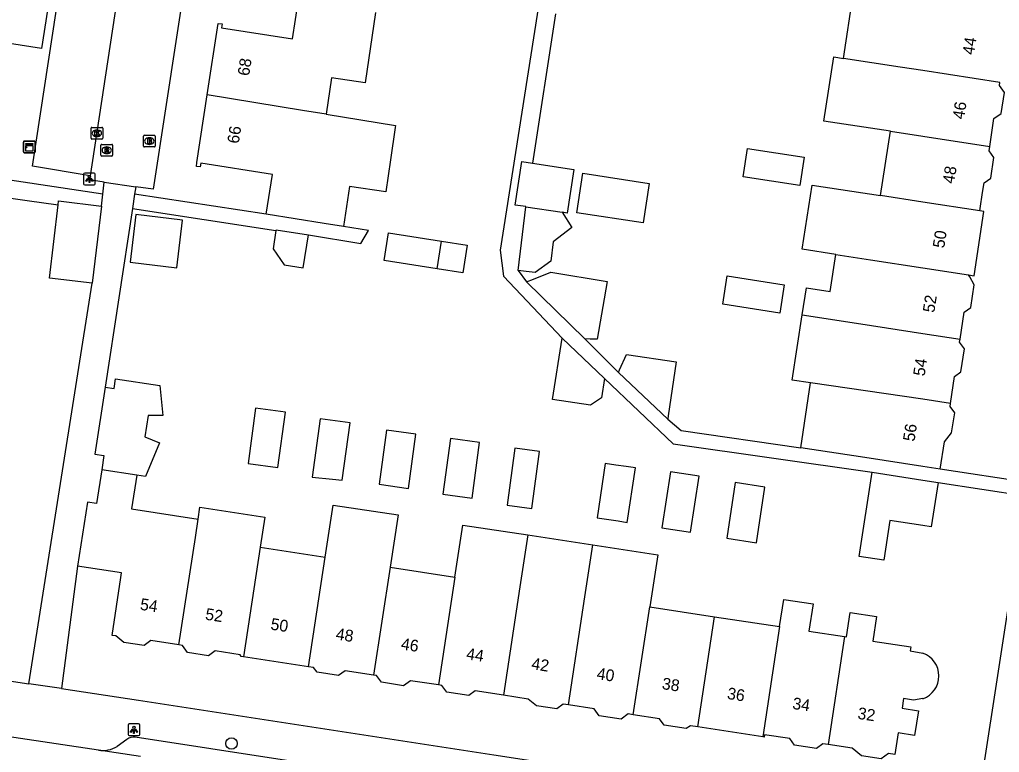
# Model space of a CAD drawing. Extents: x 161486 to 162249, y 379484 to 380829.
# Drawn here: x 161923 to 162006.5, y 380546.9 to 380609.4 of the extents above; entities that cross this region are included whole.
import ezdxf

# ---------------------------------------------------------------- set-up
doc = ezdxf.new("R2010")
doc.units = 0
for name, color, linetype in [('IMGEO_Boom', 7, 'Continuous'), ('IMGEO_Brandkraan', 7, 'Continuous'), ('IMGEO_Kast', 7, 'Continuous'), ('IMGEO_Kolk', 7, 'Continuous'), ('IMGEO_Lichtpunt', 7, 'Continuous'), ('IMGEO_Pand', 7, 'Continuous'), ('IMGEO_Pand_nummerreeks', 7, 'Continuous'), ('IMGEO_Parkeervlak_open', 7, 'Continuous'), ('IMGEO_Rijbaan_lokaal_open', 7, 'Continuous'), ('IMGEO_Rioolput', 7, 'Continuous'), ('IMGEO_Voetpad_open', 7, 'Continuous')]:
    doc.layers.add(name, color=color, linetype=linetype)

msp = doc.modelspace()

# ---------------------------------------------------------------- linework, layer by layer
at = {"layer": 'IMGEO_Boom'}
msp.add_circle((161941.042, 380547.667), 0.489, dxfattribs=at)
at = {"layer": 'IMGEO_Brandkraan'}
for p, q in [((161933.53, 380598.607), (161933.53, 380599.459)), ((161933.605, 380599.533), (161934.457, 380599.533)), ((161934.018, 380599.313), (161934.043, 380599.313)), ((161934.531, 380599.459), (161934.531, 380598.607)), ((161934.457, 380598.533), (161933.605, 380598.533)), ((161934.041, 380598.753), (161934.016, 380598.753))]:
    msp.add_line(p, q, dxfattribs=at)
for points in [[(161933.53, 380598.607), (161933.53, 380599.459)], [(161933.605, 380599.533), (161934.457, 380599.533)], [(161933.878, 380599.233), (161933.878, 380598.833), (161934.091, 380598.833)], [(161934.109, 380599.233), (161933.878, 380599.233)], [(161934.057, 380599.152), (161934.003, 380599.152), (161934.003, 380599.076)], [(161934.003, 380599.076), (161934.056, 380599.076)], [(161934.065, 380599), (161934.003, 380599), (161934.003, 380598.919)], [(161934.003, 380598.919), (161934.065, 380598.919)], [(161934.531, 380599.459), (161934.531, 380598.607)], [(161934.457, 380598.533), (161933.605, 380598.533)]]:
    msp.add_lwpolyline(points, dxfattribs=at)
for centre, radius, start, end in [((161933.607, 380599.457), 0.0765, 91.55205, 178.44795), ((161933.607, 380599.457), 0.0765, 91.55205, 178.44795), ((161934.058, 380599.114), 0.0379, 267.82845, 90.93552), ((161934.066, 380598.959), 0.0404, 269.87594, 90.50774), ((161934.097, 380599.084), 0.251, 268.66757, 293.53466), ((161934.113, 380599.088), 0.145, 59.4692, 91.53667), ((161934.138, 380599.135), 0.0922, 285.51372, 58.15012), ((161934.143, 380598.943), 0.105, 301.31148, 78.98903), ((161934.455, 380599.457), 0.0765, 1.55205, 88.44795), ((161934.455, 380599.457), 0.0765, 1.55205, 88.44795), ((161933.607, 380598.609), 0.0765, 181.55205, 268.44795), ((161933.607, 380598.609), 0.0765, 181.55205, 268.44795), ((161934.455, 380598.609), 0.0765, 271.55205, 358.44795), ((161934.455, 380598.609), 0.0765, 271.55205, 358.44795)]:
    msp.add_arc(centre, radius, start, end, dxfattribs=at)
for centre, major_axis, ratio, start_param, end_param in [((161934.017, 380599.033), (-0.387, 0.002), 0.722429, 4.712389, 7.853982), ((161934.042, 380599.033), (-0.39, 0.002), 0.717154, 1.570796, 4.712389)]:
    msp.add_ellipse(centre, major_axis=major_axis, ratio=ratio, start_param=start_param, end_param=end_param, dxfattribs=at)
at = {"layer": 'IMGEO_Kast'}
for p, q in [((161923.289, 380598.109), (161923.289, 380598.95)), ((161923.289, 380598.95), (161923.289, 380598.109)), ((161923.364, 380599.034), (161924.205, 380599.034)), ((161924.205, 380599.034), (161923.364, 380599.034)), ((161924.289, 380598.959), (161924.289, 380598.118)), ((161924.289, 380598.118), (161924.289, 380598.959)), ((161924.214, 380598.034), (161923.373, 380598.034)), ((161923.373, 380598.034), (161924.214, 380598.034))]:
    msp.add_line(p, q, dxfattribs=at)
for points in [[(161923.484, 380598.824), (161924.084, 380598.824), (161924.084, 380598.739), (161923.484, 380598.739), (161923.484, 380598.824)], [(161923.484, 380598.649), (161924.084, 380598.649), (161924.084, 380598.16), (161923.484, 380598.16), (161923.484, 380598.649)]]:
    msp.add_lwpolyline(points, dxfattribs=at)
msp.add_circle((161923.568, 380598.498), 0.0377, dxfattribs=at)
for centre, start, end in [((161923.367, 380598.956), 92.4484, 184.28452), ((161923.367, 380598.956), 92.4484, 184.28452), ((161924.211, 380598.956), 2.4484, 94.28452), ((161924.211, 380598.956), 2.4484, 94.28452), ((161923.367, 380598.112), 182.4484, 274.28452), ((161923.367, 380598.112), 182.4484, 274.28452), ((161924.211, 380598.112), 272.4484, 4.28452), ((161924.211, 380598.112), 272.4484, 4.28452)]:
    msp.add_arc(centre, 0.0779, start, end, dxfattribs=at)
at = {"layer": 'IMGEO_Kolk'}
for p, q in [((161929.058, 380599.272), (161929.058, 380600.124)), ((161929.133, 380600.198), (161929.985, 380600.198)), ((161929.546, 380599.978), (161929.571, 380599.978)), ((161930.059, 380600.124), (161930.059, 380599.272)), ((161929.985, 380599.198), (161929.133, 380599.198)), ((161929.569, 380599.418), (161929.544, 380599.418))]:
    msp.add_line(p, q, dxfattribs=at)
for points in [[(161929.058, 380599.272), (161929.058, 380600.124)], [(161929.133, 380600.198), (161929.985, 380600.198)], [(161929.379, 380599.898), (161929.502, 380599.898), (161929.502, 380599.747), (161929.632, 380599.898), (161929.796, 380599.898), (161929.65, 380599.747), (161929.803, 380599.498), (161929.651, 380599.498), (161929.566, 380599.662), (161929.502, 380599.595), (161929.502, 380599.498), (161929.379, 380599.498), (161929.379, 380599.898)], [(161930.059, 380600.124), (161930.059, 380599.272)], [(161929.985, 380599.198), (161929.133, 380599.198)]]:
    msp.add_lwpolyline(points, dxfattribs=at)
for centre, start, end in [((161929.135, 380600.122), 91.55205, 178.44795), ((161929.135, 380600.122), 91.55205, 178.44795), ((161929.983, 380600.122), 1.55205, 88.44795), ((161929.983, 380600.122), 1.55205, 88.44795), ((161929.135, 380599.274), 181.55205, 268.44795), ((161929.135, 380599.274), 181.55205, 268.44795), ((161929.983, 380599.274), 271.55205, 358.44795), ((161929.983, 380599.274), 271.55205, 358.44795)]:
    msp.add_arc(centre, 0.0765, start, end, dxfattribs=at)
for centre, major_axis, ratio, start_param, end_param in [((161929.545, 380599.698), (-0.387, 0.002), 0.722429, 4.712389, 7.853982), ((161929.57, 380599.698), (-0.39, 0.002), 0.717154, 1.570796, 4.712389)]:
    msp.add_ellipse(centre, major_axis=major_axis, ratio=ratio, start_param=start_param, end_param=end_param, dxfattribs=at)
at = {"layer": 'IMGEO_Lichtpunt'}
for p, q in [((161928.425, 380596.205), (161928.425, 380595.398)), ((161928.425, 380596.205), (161928.425, 380595.398)), ((161929.327, 380596.3), (161928.519, 380596.3)), ((161929.327, 380596.3), (161928.519, 380596.3)), ((161929.421, 380595.398), (161929.421, 380596.205)), ((161929.421, 380595.398), (161929.421, 380596.205)), ((161928.519, 380595.304), (161929.327, 380595.304)), ((161928.519, 380595.304), (161929.327, 380595.304)), ((161932.214, 380549.237), (161932.214, 380548.43)), ((161932.214, 380549.237), (161932.214, 380548.43)), ((161933.116, 380549.332), (161932.308, 380549.332)), ((161933.116, 380549.332), (161932.308, 380549.332)), ((161933.21, 380548.43), (161933.21, 380549.237)), ((161933.21, 380548.43), (161933.21, 380549.237)), ((161932.308, 380548.336), (161933.116, 380548.336)), ((161932.308, 380548.336), (161933.116, 380548.336))]:
    msp.add_line(p, q, dxfattribs=at)
for points in [[(161928.799, 380595.869), (161928.838, 380595.841), (161928.65, 380595.579), (161928.612, 380595.606), (161928.799, 380595.869)], [(161928.901, 380595.821), (161928.948, 380595.821), (161928.948, 380595.499), (161928.901, 380595.499), (161928.901, 380595.821)], [(161929.011, 380595.841), (161929.049, 380595.868), (161929.236, 380595.606), (161929.197, 380595.578), (161929.011, 380595.841)], [(161932.588, 380548.901), (161932.627, 380548.873), (161932.439, 380548.611), (161932.401, 380548.638), (161932.588, 380548.901)], [(161932.69, 380548.853), (161932.737, 380548.853), (161932.737, 380548.531), (161932.69, 380548.531), (161932.69, 380548.853)], [(161932.8, 380548.873), (161932.838, 380548.9), (161933.025, 380548.638), (161932.986, 380548.61), (161932.8, 380548.873)]]:
    msp.add_lwpolyline(points, dxfattribs=at)
for centre in [(161928.924, 380596.003), (161932.713, 380549.035)]:
    msp.add_circle(centre, 0.0994, dxfattribs=at)
for centre, start, end in [((161928.519, 380596.205), 90, 180), ((161928.519, 380596.205), 90, 180), ((161929.327, 380596.205), 0, 90), ((161929.327, 380596.205), 0, 90), ((161928.519, 380595.398), 180, 270), ((161928.519, 380595.398), 180, 270), ((161929.327, 380595.398), 270, 0), ((161929.327, 380595.398), 270, 360), ((161932.308, 380549.237), 90, 180), ((161932.308, 380549.237), 90, 180), ((161933.116, 380549.237), 0, 90), ((161933.116, 380549.237), 0, 90), ((161932.308, 380548.43), 180, 270), ((161932.308, 380548.43), 180, 270), ((161933.116, 380548.43), 270, 0), ((161933.116, 380548.43), 270, 360)]:
    msp.add_arc(centre, 0.0946, start, end, dxfattribs=at)
at = {"layer": 'IMGEO_Pand'}
for points in [[(161917.716, 380621.282), (161923.826, 380620.34), (161923.776, 380620.014), (161923.448, 380620.062), (161922.489, 380614.014), (161925.86, 380613.48), (161924.84, 380606.93), (161919.899, 380607.691), (161918.824, 380607.857), (161915.718, 380608.336)], [(161993.216, 380606.087), (161994.058, 380611.562), (161994.86, 380611.439)], [(161938.975, 380602.968), (161939.91, 380609.067), (161940.237, 380609.017), (161940.187, 380608.69), (161946.233, 380607.761), (161946.743, 380611.081)], [(161953.318, 380610.009), (161952.424, 380604.011), (161949.568, 380604.437), (161949.104, 380601.327)], [(161997.221, 380599.865), (161991.558, 380600.737), (161992.398, 380606.213), (161993.216, 380606.087)], [(162006.562, 380604.033), (162000, 380605.043), (161998.061, 380605.341), (161993.216, 380606.087)], [(162005.693, 380598.561), (162006.059, 380600.946), (162006.667, 380601.392), (162006.942, 380603.185), (162006.52, 380603.76), (162006.562, 380604.033)], [(161944, 380592.793), (161944.536, 380596.18), (161938.417, 380597.148), (161938.367, 380596.825), (161938.042, 380596.875), (161938.09, 380597.2), (161938.975, 380602.968)], [(161949.104, 380601.327), (161947.102, 380601.651), (161938.975, 380602.968)], [(161949.104, 380601.327), (161955.033, 380600.366), (161955.006, 380600.189), (161954.598, 380597.445), (161954.189, 380594.702), (161951.104, 380595.161), (161950.596, 380591.749)], [(161996.38, 380594.389), (161997.221, 380599.865)], [(161997.221, 380599.865), (162000, 380599.437), (162005.693, 380598.561)], [(161989.866, 380597.662), (161989.495, 380595.251), (161984.679, 380595.993), (161985.051, 380598.404), (161989.866, 380597.662)], [(162004.844, 380593.087), (162004.872, 380593.269), (162005.083, 380594.644), (162005.208, 380595.459), (162005.782, 380595.88), (162006.053, 380597.646), (162005.639, 380598.209), (162005.693, 380598.561)], [(161966.136, 380593.438), (161966.123, 380593.44), (161965.22, 380593.579), (161965.792, 380597.302), (161966.698, 380597.162)], [(161966.698, 380597.162), (161970.22, 380596.62), (161969.648, 380592.898), (161969.24, 380592.961)], [(161976.665, 380595.411), (161976.147, 380592.048), (161970.492, 380592.918), (161971.01, 380596.282), (161976.665, 380595.411)], [(161992.584, 380589.368), (161989.706, 380589.811), (161990.549, 380595.286), (161996.38, 380594.389)], [(161926.255, 380593.587), (161926.296, 380593.93), (161929.955, 380593.489)], [(162004.844, 380593.087), (162000, 380593.832), (161996.38, 380594.389)], [(161929.162, 380586.915), (161925.503, 380587.356), (161926.255, 380593.587)], [(161929.955, 380593.489), (161929.162, 380586.915)], [(161965.481, 380587.998), (161966.136, 380593.438)], [(161966.136, 380593.438), (161969.24, 380592.961)], [(162003.897, 380587.627), (162004.366, 380587.555), (162005.205, 380593.031), (162004.844, 380593.087)], [(161936.86, 380592.297), (161932.883, 380592.777), (161932.391, 380588.699), (161936.368, 380588.219), (161936.86, 380592.297)], [(161950.596, 380591.749), (161948.939, 380592.011), (161944, 380592.793)], [(161969.24, 380592.961), (161970.049, 380591.657), (161968.465, 380590.427), (161968.267, 380588.784), (161966.94, 380587.822), (161966.174, 380587.914), (161965.481, 380587.998)], [(161944.827, 380591.415), (161944.576, 380589.839), (161945.537, 380588.487), (161947.156, 380588.231), (161947.598, 380591.024)], [(161944.827, 380591.415), (161944.834, 380591.462), (161947.598, 380591.024)], [(161958.576, 380588.135), (161954.047, 380588.85), (161954.421, 380591.222), (161958.951, 380590.506)], [(161958.951, 380590.506), (161961.139, 380590.16), (161960.764, 380587.789), (161958.576, 380588.135)], [(161958.576, 380588.135), (161958.951, 380590.506)], [(161989.706, 380584.207), (161990.06, 380586.509), (161992.096, 380586.196), (161992.584, 380589.368)], [(161992.584, 380589.368), (161995.54, 380588.913), (162000, 380588.227), (162003.897, 380587.627)], [(161966.184, 380587.031), (161966.795, 380587.263), (161968.263, 380587.854), (161973.073, 380587.046), (161972.214, 380582.128), (161971.61, 380582.144), (161971.181, 380582.156)], [(161988.155, 380586.787), (161987.783, 380584.372), (161982.94, 380585.117), (161983.311, 380587.532), (161988.155, 380586.787)], [(162003.162, 380582.135), (162003.515, 380584.435), (162004.082, 380584.851), (162004.379, 380586.788), (162004, 380587.448), (162003.897, 380587.627)], [(161971.181, 380582.156), (161966.184, 380587.031)], [(161990.423, 380578.414), (161988.851, 380578.656), (161989.706, 380584.207)], [(161989.706, 380584.207), (161994.7, 380583.438), (162000, 380582.622), (162003.162, 380582.135)], [(161972.841, 380578.787), (161972.586, 380577.129), (161971.639, 380576.511), (161968.421, 380577.007), (161969.225, 380582.226)], [(161969.225, 380582.226), (161972.841, 380578.787)], [(162002.35, 380576.655), (162002.705, 380578.968), (162003.234, 380579.356), (162003.536, 380581.324), (162003.124, 380581.885), (162003.162, 380582.135)], [(161974.025, 380579.289), (161974.128, 380579.517), (161974.726, 380580.847), (161978.947, 380580.21), (161978.277, 380575.591), (161978.237, 380575.315)], [(161978.237, 380575.315), (161974.025, 380579.289)], [(161930.261, 380578.044), (161929.388, 380572.33), (161930.159, 380572.212), (161929.975, 380571.007)], [(161930.261, 380578.044), (161931.022, 380577.928), (161931.151, 380578.768), (161934.927, 380578.191), (161935.183, 380575.623), (161933.933, 380575.623), (161933.658, 380573.824), (161934.909, 380573.289), (161933.689, 380570.439), (161932.957, 380570.551)], [(161989.575, 380572.885), (161990.423, 380578.414)], [(162002.35, 380576.655), (162000, 380577.017), (161990.423, 380578.414)], [(162001.469, 380571.06), (162001.825, 380573.376), (162002.444, 380574.149), (162002.708, 380575.867), (162002.312, 380576.406), (162002.35, 380576.655)], [(161942.444, 380571.541), (161944.986, 380571.195), (161945.628, 380575.915), (161943.086, 380576.26), (161942.444, 380571.541)], [(161947.927, 380570.373), (161949.647, 380570.205), (161950.488, 380570.123), (161951.151, 380574.995), (161948.603, 380575.342), (161947.927, 380570.373)], [(161956.132, 380569.422), (161956.759, 380574.034), (161954.244, 380574.377), (161953.616, 380569.765), (161956.132, 380569.422)], [(161961.552, 380568.582), (161962.196, 380573.322), (161959.699, 380573.662), (161959.054, 380568.922), (161961.552, 380568.582)], [(161967.316, 380572.573), (161965.198, 380572.861), (161964.534, 380567.979), (161966.652, 380567.691), (161967.316, 380572.573)], [(162001.469, 380571.06), (162000, 380571.285), (161995.058, 380572.043), (161989.575, 380572.885)], [(161973.801, 380571.411), (161972.904, 380571.542), (161972.222, 380566.912), (161974.016, 380566.638), (161974.776, 380566.522), (161975.485, 380571.164), (161974.698, 380571.279), (161973.801, 380571.411)], [(161929.975, 380571.007), (161929.534, 380568.12), (161928.743, 380568.241), (161927.911, 380562.794)], [(161932.957, 380570.551), (161929.975, 380571.007)], [(161932.957, 380570.551), (161932.516, 380567.664), (161938.191, 380566.797)], [(161980.183, 380565.688), (161980.909, 380570.448), (161978.468, 380570.821), (161977.741, 380566.061), (161980.183, 380565.688)], [(162001.293, 380569.928), (162000.713, 380566.149), (162000, 380566.259), (161997.184, 380566.691), (161996.663, 380563.299), (161994.567, 380563.62), (161995.667, 380570.791)], [(161995.667, 380570.791), (162000, 380570.126), (162001.293, 380569.928)], [(161986.523, 380569.533), (161983.986, 380569.92), (161983.284, 380565.16), (161985.797, 380564.776), (161986.523, 380569.533)], [(161949.025, 380563.55), (161949.704, 380567.998), (161955.24, 380567.152), (161954.56, 380562.704)], [(161938.191, 380566.797), (161938.346, 380567.818), (161943.881, 380566.973), (161943.488, 380564.396)], [(161936.553, 380556.067), (161937.953, 380565.242), (161938.191, 380566.797)], [(161960.096, 380561.858), (161960.773, 380566.29), (161966.308, 380565.444)], [(161966.308, 380565.444), (161965.632, 380561.012), (161964.223, 380551.78)], [(161966.308, 380565.444), (161971.844, 380564.598)], [(161969.762, 380550.954), (161971.168, 380560.166), (161971.844, 380564.598)], [(161971.844, 380564.598), (161977.38, 380563.752), (161976.703, 380559.32)], [(161943.488, 380564.396), (161942.061, 380555.047)], [(161943.488, 380564.396), (161949.025, 380563.55)], [(161947.597, 380554.201), (161949.025, 380563.55)], [(161936.553, 380556.067), (161934.157, 380556.434), (161933.582, 380556.011), (161931.865, 380556.274), (161931.166, 380556.834), (161930.851, 380556.882), (161931.607, 380561.825), (161931.667, 380562.22), (161927.911, 380562.794)], [(161954.56, 380562.704), (161953.155, 380553.501)], [(161954.56, 380562.704), (161960.096, 380561.858)], [(161960.096, 380561.858), (161958.691, 380552.655)], [(161987.774, 380557.628), (161988.129, 380559.952), (161990.638, 380559.569), (161990.283, 380557.244), (161993.31, 380556.781)], [(161975.297, 380550.118), (161976.703, 380559.32)], [(161976.703, 380559.32), (161982.238, 380558.474)], [(161993.31, 380556.781), (161993.483, 380556.755), (161993.802, 380558.84), (161996.036, 380558.498), (161995.715, 380556.4), (161998.975, 380555.902), (161998.923, 380555.56), (162000.002, 380555.36)], [(161980.803, 380549.074), (161982.238, 380558.474)], [(161982.238, 380558.474), (161987.774, 380557.628)], [(161987.774, 380557.628), (161986.339, 380548.229)], [(161993.31, 380556.781), (161991.905, 380547.575)], [(161942.061, 380555.047), (161941.847, 380555.08), (161941.787, 380555.233), (161939.645, 380555.561), (161939.082, 380555.147), (161937.29, 380555.421), (161936.848, 380556.022), (161936.553, 380556.067)], [(161947.597, 380554.201), (161942.061, 380555.047)], [(161953.155, 380553.501), (161950.735, 380553.871), (161950.174, 380553.459), (161948.328, 380553.741), (161948.04, 380554.133), (161947.597, 380554.201)], [(161958.691, 380552.655), (161956.296, 380553.021), (161955.717, 380552.596), (161953.83, 380552.885), (161953.405, 380553.463), (161953.155, 380553.501)], [(161964.223, 380551.78), (161961.813, 380552.149), (161961.269, 380551.749), (161959.396, 380552.036), (161958.972, 380552.612), (161958.691, 380552.655)], [(161969.762, 380550.954), (161969.334, 380551.019), (161968.785, 380550.615), (161967.059, 380550.879), (161966.337, 380551.457), (161964.223, 380551.78)], [(162000, 380551.488), (161999.206, 380551.367), (161998.346, 380551.499), (161998.22, 380550.674), (161999.614, 380550.461), (161999.293, 380548.361), (161997.887, 380548.576), (161997.606, 380546.739), (161997.065, 380546.822), (161996.44, 380546.363), (161994.761, 380546.619), (161993.961, 380547.261), (161991.905, 380547.575)], [(161975.297, 380550.118), (161974.85, 380550.186), (161974.254, 380549.748), (161972.38, 380550.035), (161971.95, 380550.619), (161969.762, 380550.954)], [(161980.803, 380549.074), (161980.19, 380549.168), (161979.812, 380548.947), (161977.943, 380549.232), (161977.545, 380549.774), (161975.297, 380550.118)], [(161986.339, 380548.229), (161980.803, 380549.074)], [(161991.905, 380547.575), (161991.459, 380547.643), (161990.917, 380547.245), (161989.04, 380547.532), (161988.637, 380548.08), (161986.484, 380548.409), (161986.454, 380548.211), (161986.339, 380548.229)]]:
    msp.add_lwpolyline(points, dxfattribs=at)
msp.add_arc((161999.303, 380553.424), 2.058, 289.7959, 70.14491, dxfattribs=at)
at = {"layer": 'IMGEO_Parkeervlak_open'}
for points in [[(161938.44, 380621.627), (161934.347, 380594.923), (161932.866, 380595.14)], [(161930.191, 380595.531), (161928.938, 380595.714), (161928.997, 380596.077)]]:
    msp.add_lwpolyline(points, dxfattribs=at)
at = {"layer": 'IMGEO_Rijbaan_lokaal_open'}
for points in [[(161928.997, 380596.077), (161924.059, 380596.883), (161927.469, 380619.219)], [(161932.392, 380618.524), (161928.997, 380596.077)], [(161929.69, 380547.086), (161918.825, 380548.717)], [(161933.264, 380546.55), (161929.69, 380547.086)]]:
    msp.add_lwpolyline(points, dxfattribs=at)
at = {"layer": 'IMGEO_Rioolput'}
for p, q in [((161929.896, 380597.823), (161929.896, 380598.675)), ((161929.971, 380598.749), (161930.823, 380598.749)), ((161930.384, 380598.529), (161930.409, 380598.529)), ((161930.897, 380598.675), (161930.897, 380597.823)), ((161930.823, 380597.749), (161929.971, 380597.749)), ((161930.407, 380597.969), (161930.382, 380597.969))]:
    msp.add_line(p, q, dxfattribs=at)
for points in [[(161929.896, 380597.823), (161929.896, 380598.675)], [(161929.971, 380598.749), (161930.823, 380598.749)], [(161930.485, 380598.447), (161930.233, 380598.449), (161930.233, 380598.049)], [(161930.233, 380598.049), (161930.357, 380598.049), (161930.357, 380598.211), (161930.368, 380598.211)], [(161930.411, 380598.368), (161930.357, 380598.368), (161930.357, 380598.287)], [(161930.357, 380598.287), (161930.409, 380598.287)], [(161930.415, 380598.182), (161930.486, 380598.049), (161930.626, 380598.049), (161930.561, 380598.175)], [(161930.897, 380598.675), (161930.897, 380597.823)], [(161930.823, 380597.749), (161929.971, 380597.749)]]:
    msp.add_lwpolyline(points, dxfattribs=at)
for centre, radius, start, end in [((161929.973, 380598.673), 0.0765, 91.55205, 178.44795), ((161929.973, 380598.673), 0.0765, 91.55205, 178.44795), ((161930.367, 380598.158), 0.0533, 26.02933, 88.69889), ((161930.393, 380598.476), 0.19, 274.7715, 282.96867), ((161930.417, 380598.272), 0.0964, 77.00612, 93.18647), ((161930.431, 380598.329), 0.0378, 276.66336, 79.67722), ((161930.484, 380598.337), 0.109, 350.36119, 89.41601), ((161930.482, 380598.337), 0.112, 277.58423, 350.98172), ((161930.466, 380598.122), 0.108, 29.51342, 73.79051), ((161930.821, 380598.673), 0.0765, 1.55205, 88.44795), ((161930.821, 380598.673), 0.0765, 1.55205, 88.44795), ((161929.973, 380597.825), 0.0765, 181.55205, 268.44795), ((161929.973, 380597.825), 0.0765, 181.55205, 268.44795), ((161930.821, 380597.825), 0.0765, 271.55205, 358.44795), ((161930.821, 380597.825), 0.0765, 271.55205, 358.44795)]:
    msp.add_arc(centre, radius, start, end, dxfattribs=at)
for centre, major_axis, ratio, start_param, end_param in [((161930.383, 380598.249), (-0.387, 0.002), 0.722429, 4.712389, 7.853982), ((161930.408, 380598.249), (-0.39, 0.002), 0.717154, 1.570796, 4.712389)]:
    msp.add_ellipse(centre, major_axis=major_axis, ratio=ratio, start_param=start_param, end_param=end_param, dxfattribs=at)
at = {"layer": 'IMGEO_Voetpad_open'}
for points in [[(161970.745, 380633.249), (161969.705, 380626.52), (161963.937, 380589.722), (161964.224, 380587.502), (161969.225, 380582.226)], [(161968.663, 380609.885), (161966.698, 380597.162)], [(161930.073, 380594.51), (161896.647, 380599.526), (161896.401, 380598.035), (161906.212, 380596.519)], [(161930.073, 380594.51), (161930.191, 380595.531)], [(161930.191, 380595.531), (161932.866, 380595.14)], [(161932.866, 380595.14), (161932.769, 380594.504)], [(161922.227, 380594.176), (161923.617, 380593.973), (161926.255, 380593.587)], [(161929.955, 380593.489), (161930.073, 380594.51)], [(161932.769, 380594.504), (161932.583, 380593.281)], [(161944, 380592.793), (161932.769, 380594.504)], [(161932.583, 380593.281), (161930.261, 380578.044)], [(161932.583, 380593.281), (161944.827, 380591.415)], [(161947.598, 380591.024), (161952.067, 380590.312), (161952.709, 380591.415), (161950.596, 380591.749)], [(161965.481, 380587.998), (161966.184, 380587.031)], [(161923.744, 380552.759), (161929.162, 380586.915)], [(161971.181, 380582.156), (161974.025, 380579.289)], [(161972.841, 380578.787), (161978.692, 380573.217), (161995.667, 380570.791)], [(161978.237, 380575.315), (161979.387, 380574.363), (161989.575, 380572.885)], [(162008.935, 380569.909), (162001.469, 380571.06)], [(162001.293, 380569.928), (162008.76, 380568.777)], [(162004.779, 380542.949), (162008.76, 380568.777)], [(161842.113, 380565.304), (161845.302, 380564.812), (161850.616, 380563.993), (161887.994, 380558.235), (161920.738, 380553.21), (161923.744, 380552.759)], [(161927.911, 380562.794), (161926.533, 380552.341)], [(161926.533, 380552.341), (161923.744, 380552.759)], [(161926.533, 380552.341), (161933.1, 380551.357), (161963.411, 380546.705), (161989.926, 380542.639), (162000, 380540.965), (162001.608, 380540.698)], [(161932.106, 380548.019), (161931.292, 380547.414)], [(161998.077, 380538.155), (161932.83, 380548.205)]]:
    msp.add_lwpolyline(points, dxfattribs=at)
for centre, radius, start, end in [((161932.707, 380547.181), 1.032, 83.16509, 125.651), ((161930.026, 380549.523), 2.46, 262.16094, 300.98117)]:
    msp.add_arc(centre, radius, start, end, dxfattribs=at)

# ---------------------------------------------------------------- texts
at = {"layer": 'IMGEO_Pand_nummerreeks'}
for s, rotation, p in [('44', 81.25114, (162004.346, 380606.34)), ('68', 81.27979, (161942.535, 380604.545)), ('46', 81.25114, (162003.501, 380600.846)), ('66', 81.27979, (161941.65, 380598.771)), ('48', 81.25114, (162002.657, 380595.354)), ('50', 81.25114, (162001.811, 380589.86)), ('52', 81.25114, (162000.965, 380584.359)), ('54', 81.57152, (162000.142, 380578.948)), ('56', 81.26871, (161999.275, 380573.375)), ('54', 351.36035, (161933.194, 380559.075)), ('52', 351.3598, (161938.754, 380558.23)), ('50', 351.36035, (161944.323, 380557.384)), ('48', 351.36035, (161949.886, 380556.539)), ('46', 351.36035, (161955.446, 380555.694)), ('44', 351.3598, (161961.009, 380554.849)), ('42', 351.3598, (161966.569, 380554.004)), ('40', 351.3598, (161972.138, 380553.158)), ('38', 351.36035, (161977.7, 380552.312)), ('36', 351.36035, (161983.26, 380551.468)), ('34', 351.3598, (161988.823, 380550.623)), ('32', 351.36035, (161994.383, 380549.778))]:
    msp.add_text(s, height=1, rotation=rotation, dxfattribs=at).set_placement(p)

doc.saveas('drawing.dxf')
